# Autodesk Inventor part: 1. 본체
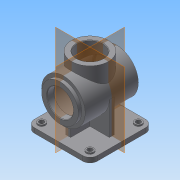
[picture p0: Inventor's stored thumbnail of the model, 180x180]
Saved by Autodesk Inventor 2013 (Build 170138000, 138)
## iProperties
Created: 2015-07
Part Number: 1. 본체
Material: 일반
Document SubType Name: Modeling
Designer: Administrator
Density: 1 g/cm^3
Author: Administrator
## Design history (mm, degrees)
sketch "스케치1"
  geometry: C1 r 45 at (0, 0); 1 further point
  constraints: 1 centre point, 1 coincident
  dimensions: "d0" = 90 diameter of C1
extrude "돌출1" new body sketch "스케치1" distance "d2" = 110; taper "d3" = 0 deg
sketch "스케치2"
  geometry: C1 r 45 at (0, 0) reference; C2 r 38 at (0, 0); 1 further point
  constraints: 1 centre point, 1 coincident
  dimensions: "d4" = 76 diameter of C2
extrude "돌출2" join sketch "스케치2" distance "d6" = 7; taper "d7" = 0 deg
node "작업점1"
  node "작업 평면1"
  node "작업 평면2"
sketch "스케치3"
  geometry: C1 r 38 at (0, 55); 2 further points
  constraints: 1 centre point, 1 coincident
  dimensions: "d9" = 76 diameter of C1
extrude "돌출3" join sketch "스케치3" stored distance "d11" = 7; taper "d12" = 0 deg
sketch "스케치4"
  geometry: C1 r 38 at (0, 0) reference; C2 r 27 at (0, 0); 1 further point
  constraints: 1 centre point, 1 coincident
  dimensions: "d13" = 54 diameter of C2
extrude "돌출4" cut sketch "스케치4" distance "d15" = 62; taper "d16" = 0 deg
node "작업 평면3"
sketch "스케치5"
  geometry: L1 (-38, 24.104)-(-38, 62) reference; L2 (-38, 62)-(-27, 62) reference; L3 (-27, 62)-(-27, 0) reference; L4 (-27, 0)-(27, 0) reference; L5 (27, 0)-(27, 62) reference; L6 (27, 62)-(38, 62) reference; L7 (38, 62)-(38, 24.104) reference; L8 (-65, -68)-(65, -68); L9 (65, -68)-(65, -78); L10 (65, -78)-(-65, -78); L11 (-65, -78)-(-65, -68); A1 r 45 centre (0, 0) between (-38, 24.104) and (38, 24.104) reference; 3 further points
  constraints: 8 end point, 2 parallel, 1 horizontal, 1 midpoint, 1 perpendicular, 1 point on circle, 1 vertical alignment
  dimensions: "d18" = 130 distance of L9.end L10.end; "d20" = 10 distance of L8.end L9.end; "d21" = 140 distance between parallel lines of L10 L6
extrude "돌출5" join sketch "스케치5" distance "d22" = 65; taper "d24" = 0 deg; dims "d23" = 65, "d25" = 0
sketch "스케치7"
  geometry: L1 (20, 70)-(110, 70); L2 (110, 70)-(110, 60); L3 (110, 60)-(20, 60); L4 (20, 60)-(20, 70); L5 (130, 0)-(130, 130) reference; L6 (130, 130)-(0, 130) reference; 5 further points
  constraints: 8 end point, 4 midpoint, 2 parallel, 1 horizontal, 1 horizontal alignment, 1 perpendicular, 1 vertical alignment
  dimensions: "d29" = 90 distance of L1.start L1.end; "d31" = 10 distance of L3.end L1.start
extrude "돌출6" join sketch "스케치7" stored distance "d32" = 65; taper "d33" = 0 deg
sketch "스케치8"
  geometry: L1 (20, 60)-(20, 70) reference; L2 (20, 70)-(110, 70) reference; L3 (110, 70)-(110, 60) reference; L4 (110, 60)-(20, 60) reference; L5 (0, 130)-(130, 130) reference; L6 (130, 130)-(130, 0) reference; L7 (130, 0)-(0, 0) reference; L8 (0, 0)-(0, 130) reference; L9 (60, 110)-(70, 110); L10 (70, 110)-(70, 20); L11 (70, 20)-(60, 20); L12 (60, 20)-(60, 110); 5 further points
  constraints: 8 end point, 4 midpoint, 2 parallel, 1 horizontal, 1 horizontal alignment, 1 perpendicular, 1 vertical alignment
  dimensions: "d34" = 90 distance of L9.end L10.end; "d36" = 10 distance of L9.start L9.end
extrude "돌출7" join sketch "스케치8" stored distance "d37" = 65; taper "d38" = 0 deg
sketch "스케치9"
  geometry: L1 (38, 117)-(38, 110) reference; L2 (38, 110)-(45, 110) reference; L3 (45, 110)-(45, 93) reference; L4 (45, 93)-(62, 93) reference; L5 (62, 93)-(62, 82) reference; L6 (62, 82)-(0, 82) reference; L7 (0, 82)-(0, 28) reference; L8 (0, 28)-(62, 28) reference; L9 (62, 28)-(62, 17) reference; L10 (62, 17)-(45, 17) reference; L11 (45, 17)-(45, 0) reference; L12 (45, 0)-(-45, 0) reference; L13 (-45, 0)-(-45, 10) reference; L14 (-45, 10)-(-68, 10) reference; L15 (-68, 10)-(-68, -10) reference; L16 (-68, -10)-(-78, -10) reference; L17 (-78, -10)-(-78, 120) reference; L18 (-78, 120)-(-68, 120) reference; L19 (-68, 120)-(-68, 100) reference; L20 (-68, 100)-(-45, 100) reference; L21 (-45, 100)-(-45, 110) reference; L22 (-45, 110)-(-38, 110) reference; L23 (-38, 110)-(-38, 117) reference; L24 (-38, 117)-(38, 117) reference; L25 (0, 0)-(0, 117); L26 (27, 117)-(27, 103); L27 (27, 103)-(40, 103); L28 (40, 103)-(40, 7); L29 (40, 7)-(0, 7)
  constraints: 10 end point, 2 parallel, 2 perpendicular, 2 point on line, 1 midpoint
  dimensions: "d39" = 80 diameter of L28 L25; "d41" = 7 distance between parallel lines of L12 L29; "d42" = 54 diameter of L26 L25; "d43" = 14 distance of L26.start L26.end
revolve "회전1" sketch "스케치9" stored, may be unused: angle "d44" = 90 deg
fillet "모깎기1" dims "d45" = 3
chamfer "모따기1" distance "d46" = 1; stored, may be unused: second distance "d47" = 2, angle "d48" = 45 deg
fillet "모깎기2" dims "d49" = 15
sketch "스케치10"
  geometry: L1 (115, 115)-(115, 15) reference; L2 (100, 0)-(0, 0) reference; L3 (-15, 15)-(-15, 115) reference; L4 (0, 130)-(100, 130) reference; L5 (45, 20)-(45, 60) reference; L6 (45, 60)-(5, 60) reference; L7 (5, 60)-(5, 70) reference; L8 (5, 70)-(45, 70) reference; L9 (45, 70)-(45, 110) reference; L10 (45, 110)-(55, 110) reference; L11 (55, 110)-(55, 70) reference; L12 (55, 70)-(95, 70) reference; L13 (95, 70)-(95, 60) reference; L14 (95, 60)-(55, 60) reference; L15 (55, 60)-(55, 20) reference; L16 (55, 20)-(45, 20) reference; C1 r 7.5 at (0, 115); C2 r 7.5 at (100, 115); C3 r 7.5 at (0, 15); C4 r 7.5 at (100, 15); A1 r 15 centre (100, 115) between (115, 115) and (100, 130) reference; A2 r 15 centre (100, 15) between (100, 0) and (115, 15) reference; A3 r 15 centre (0, 15) between (-15, 15) and (0, 0) reference; A4 r 15 centre (0, 115) between (0, 130) and (-15, 115) reference; 1 further point
  constraints: 4 centre point, 4 coincident, 3 equal radius
  dimensions: "d50" = 15 diameter of C1
extrude "돌출8" join sketch "스케치10" distance "d52" = 3; taper "d53" = 0 deg
sketch "스케치11"
  geometry: L1 (45, 5)-(45, 45) reference; L2 (45, 45)-(5, 45) reference; L3 (5, 45)-(5, 55) reference; L4 (5, 55)-(45, 55) reference; L5 (45, 55)-(45, 95) reference; L6 (45, 95)-(55, 95) reference; L7 (55, 95)-(55, 55) reference; L8 (55, 55)-(95, 55) reference; L9 (95, 55)-(95, 45) reference; L10 (95, 45)-(55, 45) reference; L11 (55, 45)-(55, 5) reference; L12 (55, 5)-(45, 5) reference; C1 r 7.5 at (0, 0) reference; C2 r 7.5 at (0, 100) reference; C3 r 7.5 at (100, 100) reference; C4 r 7.5 at (100, 0) reference; 5 further points
  constraints: 4 coincident
hole "구멍1" sketch "스케치11" at (0, 100), (100, 100), (100, 0), (0, 0) diameter "d54" = 10; stored, may be unused: countersink angle "d58" = 90 deg, drill point angle "d60" = 118 deg; dims "d55" = 6, "d56" = 4, "d57" = 2, "d59" = 8
node "솔리드1"
node "투영된 루프1"
node "투영된 루프2"
node "절단 모서리 투영1"
node "절단 모서리 투영3"
node "절단 모서리 투영4"
node "절단 모서리 투영5"
node "절단 모서리 투영6"
other parameters: "d8" = 62, "d17" = -78
